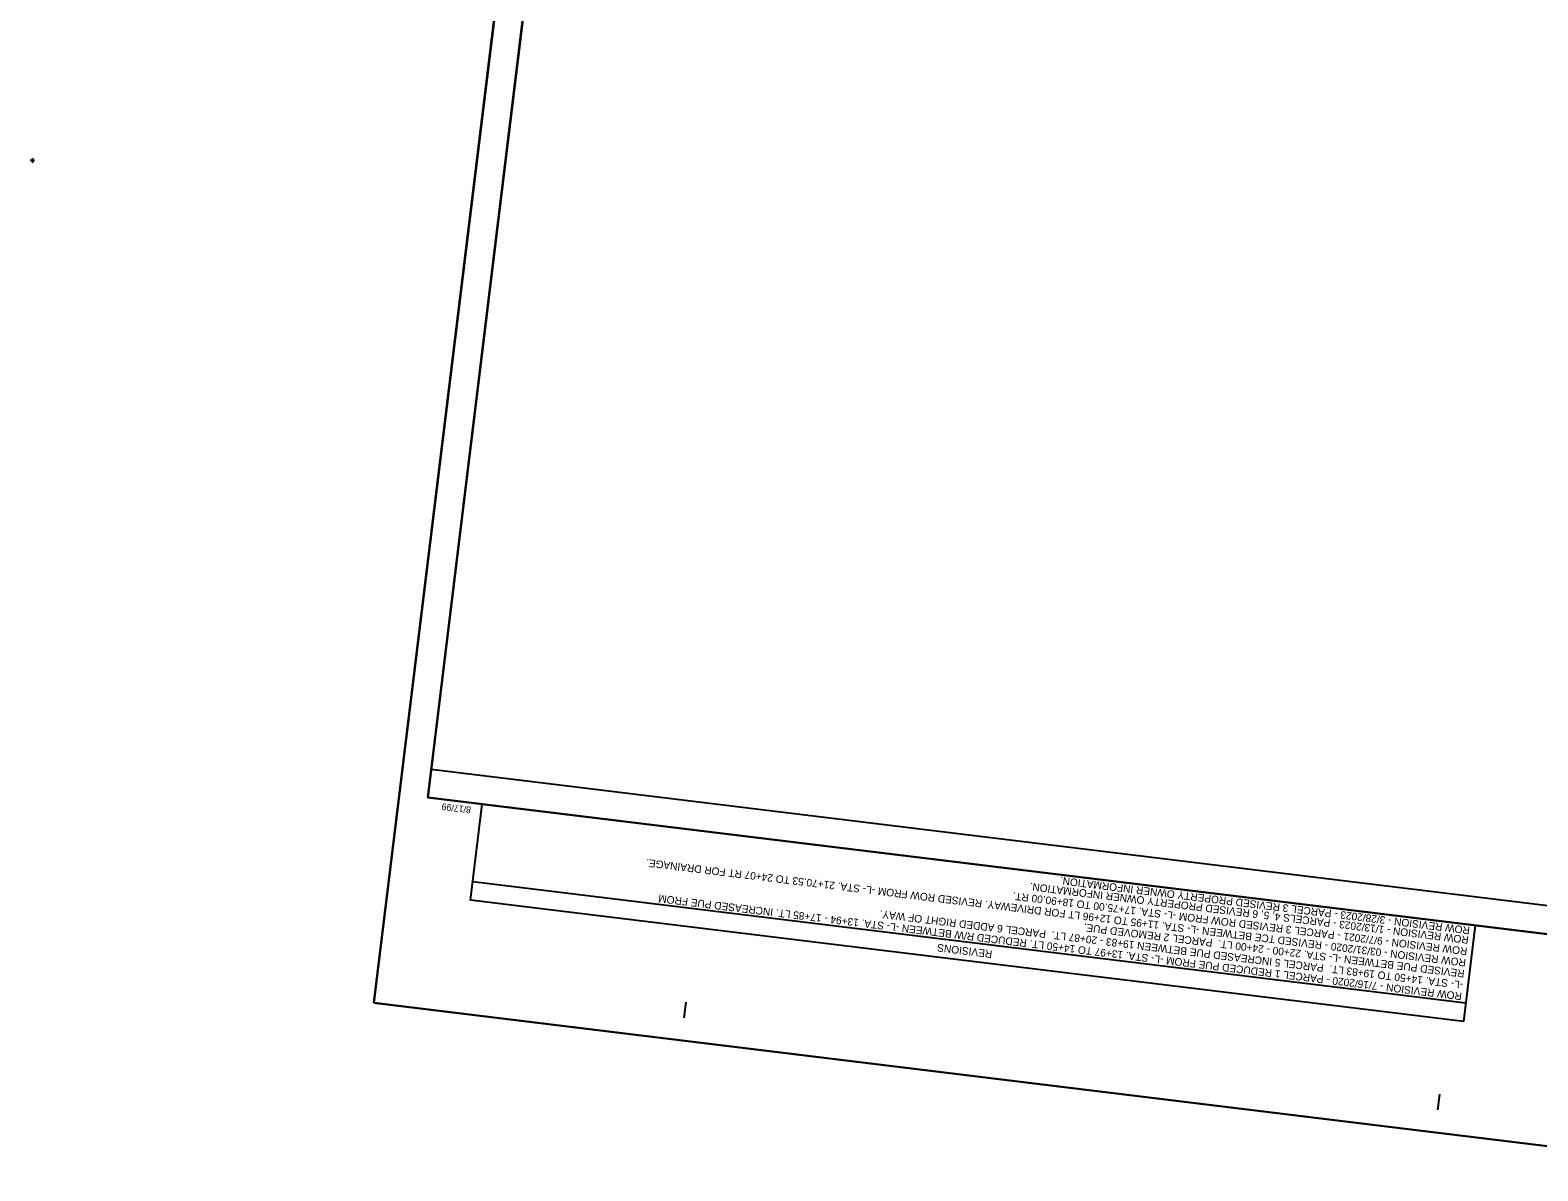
# Model space of a CAD drawing. Extents: x 480344 to 482186, y 488805 to 491553.
# Drawn here: x 480344 to 481536, y 488805 to 489707 of the extents above; entities that cross this region are included whole.
import ezdxf

# ---------------------------------------------------------------- set-up
doc = ezdxf.new("R2010")
doc.units = 0
for name, color, linetype in [('Old_Level_1', 7, 'Continuous'), ('Sheet Block Revision CELL', 7, 'Continuous'), ('Sheet Cutting Line CELL', 7, 'Continuous'), ('Sheet Layout Plan Border', 7, 'Continuous'), ('Sheet Plan CELL', 7, 'Continuous'), ('Sheet Plan Layout CELL', 7, 'Continuous'), ('Sheet Plot Border Inside CELL', 7, 'Continuous'), ('Sheet Plot Border Outside CELL', 7, 'Continuous')]:
    doc.layers.add(name, color=color, linetype=linetype)

msp = doc.modelspace()

# ---------------------------------------------------------------- linework, layer by layer
at = {"layer": 'Old_Level_1'}
for p, q in [((480347.5, 489603.9), (480344, 489603.9)), ((480345.8, 489605.7), (480345.8, 489602.2))]:
    msp.add_line(p, q, dxfattribs=at)
at = {"layer": 'Sheet Block Revision CELL'}
msp.add_line((481478.7, 488937.7), (480693.9, 489033.5), dxfattribs=at)
msp.add_lwpolyline([(481477, 488923.2), (480692.1, 489019.1), (480701.4, 489095.1), (481486.2, 488999.2)], close=True, dxfattribs=at)
at = {"layer": 'Sheet Cutting Line CELL'}
for p, q in [((480819.9, 490608.9), (480615.8, 488937.8)), ((480615.8, 488937.8), (481702.7, 488805.1))]:
    msp.add_line(p, q, dxfattribs=at)
at = {"layer": 'Sheet Layout Plan Border'}
msp.add_lwpolyline([(481703.2, 488995.3), (481861.7, 490292.7), (481782.3, 490302.4), (481802.9, 490471.7), (481574.8, 490460.7), (481089.8, 490520), (481007.7, 490530), (480988.1, 490369.7), (480815.9, 490390.7), (480661, 489122.6)], close=True, dxfattribs=at)
at = {"layer": 'Sheet Plan CELL'}
for p, q in [((480658.3, 489100.3), (480815.9, 490390.7)), ((480658.3, 489100.4), (480658.3, 489100.4)), ((481700.5, 488973.1), (480658.3, 489100.3)), ((480861.1, 488926), (480862.6, 488938.4)), ((481456.7, 488853.3), (481458.2, 488865.7))]:
    msp.add_line(p, q, dxfattribs=at)
msp.add_lwpolyline([(480840.1, 490589.3), (480658.3, 489100.4), (481700.5, 488973.1), (481882.4, 490462)], close=True, dxfattribs=at)
at = {"layer": 'Sheet Plan Layout CELL'}
for p, q in [((480811.1, 490351.8), (480658.3, 489100.3)), ((480658.3, 489100.3), (481700.5, 488973.1))]:
    msp.add_line(p, q, dxfattribs=at)
at = {"layer": 'Sheet Plot Border Inside CELL'}
msp.add_lwpolyline([(481705.5, 488972.4), (481887.3, 490461.4), (480840.1, 490589.3), (480658.3, 489100.3)], close=True, dxfattribs=at)
at = {"layer": 'Sheet Plot Border Outside CELL'}
msp.add_lwpolyline([(480615.8, 488937.8), (480819.9, 490608.9), (481906.8, 490476.1), (481702.7, 488805.1)], close=True, dxfattribs=at)

# ---------------------------------------------------------------- texts
at = {"layer": 'Sheet Block Revision CELL'}
for s, p in [('ROW REVISION - 03/31/2020 - REVISED TCE BETWEEN -L- STA. 11+95 TO 12+96 LT FOR DRIVEWAY. REVISED ROW FROM -L- STA. 21+70.53 TO 24+07 RT FOR DRAINAGE.', (481479.2, 488972.5)), ('ROW REVISION - 1/13/2023 - PARCELS 4, 5, 6 REVISED PROPERTY OWNER INFORMATION. ', (481481.4, 488990.5)), ('ROW REVISION - 3/28/2023 - PARCEL 3 REVISED PROPERTY OWNER INFORMATION. ', (481482.3, 488998)), ('ROW REVISION - 7/16/2020 - PARCEL 1 REDUCED PUE FROM -L- STA. 13+97 TO 14+50 LT. REDUCED R/W BETWEEN -L- STA. 13+94 - 17+85 LT. INCREASED PUE FROM ', (481476, 488945.9)), ('ROW REVISION - 9/7/2021 - PARCEL 3 REVISED ROW FROM -L- STA. 17+75.00 TO 18+90.00 RT. ', (481480.3, 488981.5)), ('-L- STA. 14+50 TO 19+83 LT.  PARCEL 5 INCREASED PUE BETWEEN 19+83 - 20+87 LT.  PARCEL 6 ADDED RIGHT OF WAY.', (481477, 488954.8)), ('REVISED PUE BETWEEN -L- STA. 22+00 - 24+00 LT.  PARCEL 2 REMOVED PUE.', (481478.1, 488963.8)), ('REVISIONS', (481104.8, 488979.3))]:
    msp.add_text(s, height=6, rotation=173.0365, dxfattribs=at).set_placement(p)
at = {"layer": 'Sheet Plan CELL'}
msp.add_text('8/17/99', height=5.25, rotation=173.0365, dxfattribs=at).set_placement((480692.8, 489092.9))

doc.saveas('drawing.dxf')
